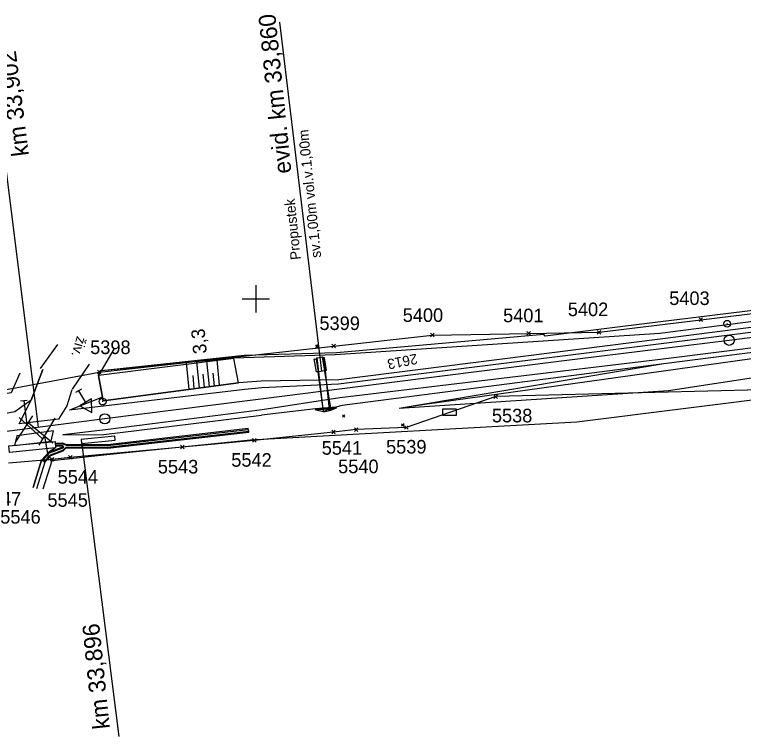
# Model space of a CAD drawing. Extents: x -805011 to -803920, y -1150790 to -1150234.
# Drawn here: x -804735.5 to -804628.3, y -1150564.4 to -1150458.2 of the extents above; entities that cross this region are included whole.
import ezdxf

# ---------------------------------------------------------------- set-up
doc = ezdxf.new("R2010")
doc.units = 0
for name, color, linetype in [('0381KM032-037P - Vrstva 1', 7, 'Continuous'), ('0381KM032-037P - Vrstva 13', 7, 'Continuous'), ('0381KM032-037P - Vrstva 17', 7, 'Continuous'), ('0381KM032-037P - Vrstva 19', 7, 'Continuous'), ('0381KM032-037P - Vrstva 25', 7, 'Continuous'), ('0381KM032-037P - Vrstva 4', 7, 'Continuous'), ('0381KM032-037P - Vrstva 43', 7, 'Continuous'), ('0381KM032-037P - Vrstva 48', 7, 'Continuous'), ('0381KM032-037P - Vrstva 49', 7, 'Continuous'), ('0381KM032-037P - Vrstva 51', 7, 'Continuous'), ('0381KM032-037P - Vrstva 57', 7, 'Continuous'), ('0381KM032-037P - Vrstva 7', 7, 'Continuous'), ('0381KM032-037P - Vrstva 9', 7, 'Continuous'), ('krizky_1000 - Vrstva 1', 7, 'Continuous'), ('szdc - hran DP', 7, 'Continuous'), ('szdc - szdc_cislo', 7, 'Continuous'), ('szdc - szdc_krizek', 7, 'Continuous')]:
    doc.layers.add(name, color=color, linetype=linetype)

msp = doc.modelspace()

# ---------------------------------------------------------------- linework, layer by layer
at = {"layer": '0381KM032-037P - Vrstva 1'}
msp.add_lwpolyline([(-804485.9, -1150487.74), (-804508.11, -1150490.55), (-804529.67, -1150493.3), (-804537.63, -1150494.31), (-804546.61, -1150495.46), (-804554.2, -1150496.42), (-804564.05, -1150497.67), (-804586.01, -1150500.48), (-804607.92, -1150503.26), (-804630.35, -1150506.11), (-804652.65, -1150508.9), (-804675.7, -1150511.78), (-804698.85, -1150514.71), (-804701.61, -1150515.06), (-804722.18, -1150517.67), (-804729.05, -1150518.54), (-804735.1, -1150519.31), (-804744.56, -1150520.5), (-804767.65, -1150523.46), (-804791, -1150526.42)], dxfattribs=at)
at = {"layer": '0381KM032-037P - Vrstva 13'}
for points in [[(-804703.22, -1150508.8), (-804723.12, -1150511.26), (-804722.46, -1150514.99), (-804702.53, -1150512.35), (-804703.22, -1150508.8)], [(-804732.2, -1150527.92), (-804730.97, -1150524.01), (-804730.13, -1150523.06), (-804728.33, -1150522.36), (-804727.9, -1150521.95), (-804721.78, -1150521.96), (-804701.01, -1150519.63), (-804701.03, -1150519.46), (-804701.1, -1150519.22), (-804701.1, -1150519.05)], [(-804731.12, -1150523.92), (-804730.21, -1150522.94), (-804728.39, -1150522.25), (-804727.91, -1150521.81), (-804721.79, -1150521.85), (-804701.03, -1150519.46)], [(-804729.45, -1150521.32), (-804728.46, -1150521.31), (-804727.91, -1150521.54), (-804721.8, -1150521.59), (-804701.1, -1150519.22)], [(-804729.38, -1150521.22), (-804728.48, -1150521.2), (-804727.92, -1150521.41), (-804721.8, -1150521.43), (-804701.1, -1150519.05)], [(-804732.74, -1150527.78), (-804731.51, -1150523.73), (-804730.41, -1150522.51), (-804728.49, -1150521.85), (-804728.25, -1150521.76), (-804728.53, -1150521.71), (-804729.44, -1150521.68)], [(-804731.32, -1150523.78), (-804730.35, -1150522.68), (-804728.48, -1150521.99), (-804728.25, -1150521.76), (-804728.5, -1150521.58), (-804729.42, -1150521.57)], [(-804729.38, -1150521.22), (-804729.45, -1150521.32), (-804729.42, -1150521.57), (-804729.44, -1150521.68)], [(-804731.51, -1150523.73), (-804731.32, -1150523.78), (-804731.12, -1150523.92), (-804730.97, -1150524.01)]]:
    msp.add_lwpolyline(points, dxfattribs=at)
at = {"layer": '0381KM032-037P - Vrstva 17'}
for p, q in [((-804731.66, -1150510.27), (-804729.1, -1150506.73)), ((-804726.96, -1150513.28), (-804724.46, -1150509.62))]:
    msp.add_line(p, q, dxfattribs=at)
for points in [[(-804552.89, -1150488.84), (-804553.29, -1150492.03), (-804593.3, -1150497.6), (-804640.86, -1150503.43), (-804657.42, -1150505.51), (-804657.62, -1150505.23), (-804688.14, -1150507.97), (-804701.71, -1150508.32), (-804722.68, -1150510.59), (-804720.85, -1150507.4)], [(-804731.29, -1150527.98), (-804729.95, -1150523.81), (-804721.9, -1150522.89), (-804700.75, -1150520.73), (-804652.77, -1150518.11), (-804588.21, -1150510.02), (-804572.8, -1150507.15), (-804561.55, -1150507.7), (-804553.92, -1150509.55)], [(-804734.71, -1150510.96), (-804735.96, -1150513.84), (-804741.77, -1150514.83), (-804760.36, -1150517.2), (-804793.92, -1150520.9)]]:
    msp.add_lwpolyline(points, dxfattribs=at)
at = {"layer": '0381KM032-037P - Vrstva 19'}
for p, q in [((-804690.3, -1150510.66), (-804696.47, -1150459.27)), ((-804690.02, -1150516.61), (-804690.96, -1150508.7)), ((-804688.92, -1150516.37), (-804690.16, -1150508.54)), ((-804690.09, -1150516.25), (-804690.83, -1150510.72)), ((-804689.77, -1150510.59), (-804689.19, -1150516.28)), ((-804690.02, -1150516.61), (-804688.92, -1150516.37))]:
    msp.add_line(p, q, dxfattribs=at)
for points in [[(-804689.58, -1150510.57), (-804689.77, -1150510.59), (-804690.83, -1150510.72), (-804691.04, -1150510.74), (-804691.4, -1150508.85), (-804691.12, -1150508.86), (-804690.83, -1150510.72)], [(-804691.12, -1150508.86), (-804690.96, -1150508.7), (-804690.59, -1150508.62), (-804690.16, -1150508.54), (-804690.08, -1150508.63)], [(-804689.58, -1150510.57), (-804689.88, -1150508.68), (-804690.08, -1150508.63), (-804689.77, -1150510.59)], [(-804688.16, -1150516.11), (-804688.92, -1150516.37), (-804689.19, -1150516.28), (-804690.09, -1150516.25), (-804690.02, -1150516.61), (-804691.14, -1150516.38)]]:
    msp.add_lwpolyline(points, dxfattribs=at)
msp.add_lwpolyline([(-804688.22, -1150515.92), (-804688.16, -1150516.11), (-804691.14, -1150516.38), (-804691.19, -1150516.18)], close=True, dxfattribs=at)
at = {"layer": '0381KM032-037P - Vrstva 25'}
msp.add_lwpolyline([(-804672.5, -1150517.17), (-804672.5, -1150516.17), (-804670.5, -1150516.17), (-804670.5, -1150517.17), (-804672.5, -1150517.17)], dxfattribs=at)
at = {"layer": '0381KM032-037P - Vrstva 4'}
for p, q in [((-804738.68, -1150465.82), (-804731.99, -1150518.9)), ((-804699.22, -1150512.12), (-804702.53, -1150512.35)), ((-804733.62, -1150514.94), (-804734.61, -1150515.06)), ((-804734.11, -1150515), (-804733.68, -1150518.47)), ((-804691.19, -1150516.18), (-804699.14, -1150517.12)), ((-804688.22, -1150515.92), (-804691.19, -1150516.18)), ((-804732.83, -1150517.21), (-804735.37, -1150521.05)), ((-804731.4, -1150520.55), (-804734.81, -1150517.46)), ((-804731.84, -1150521.52), (-804729.49, -1150517.55)), ((-804729.05, -1150518.54), (-804735.1, -1150519.31)), ((-804733.43, -1150518.25), (-804729.87, -1150521.17)), ((-804730.44, -1150523.66), (-804731.05, -1150520.21)), ((-804730.93, -1150523.75), (-804729.95, -1150523.57))]:
    msp.add_line(p, q, dxfattribs=at)
for points in [[(-804593.11, -1150499.86), (-804640.49, -1150505.94), (-804687.8, -1150511.91), (-804699.22, -1150512.12)], [(-804593.19, -1150500.62), (-804640.38, -1150506.6), (-804687.82, -1150512.54), (-804699.1, -1150513.12)], [(-804592.89, -1150502.96), (-804640.05, -1150508.88), (-804687.61, -1150514.59), (-804699.07, -1150516.32)], [(-804592.67, -1150503.55), (-804639.94, -1150509.55), (-804687.3, -1150515.71), (-804688.22, -1150515.92)], [(-804702.53, -1150512.35), (-804722.46, -1150514.99), (-804722.57, -1150514.49)], [(-804699.1, -1150513.12), (-804701.6, -1150513.32), (-804727.4, -1150516.37)], [(-804722.57, -1150514.49), (-804727.4, -1150516.37)], [(-804699.07, -1150516.32), (-804722.12, -1150519.29), (-804728.4, -1150520.02), (-804722.36, -1150519.97), (-804699.14, -1150517.12)]]:
    msp.add_lwpolyline(points, dxfattribs=at)
at = {"layer": '0381KM032-037P - Vrstva 43'}
msp.add_lwpolyline([(-804736.33, -1150521.65), (-804729.5, -1150520.98), (-804729.45, -1150521.92), (-804736.22, -1150522.62)], close=True, dxfattribs=at)
at = {"layer": '0381KM032-037P - Vrstva 48'}
for p, q in [((-804706.81, -1150512.92), (-804707.19, -1150509.11)), ((-804705.32, -1150512.72), (-804705.69, -1150508.97)), ((-804709.78, -1150513.31), (-804710.17, -1150509.4)), ((-804708.29, -1150513.12), (-804708.68, -1150509.26)), ((-804709.04, -1150513.21), (-804709.23, -1150511.27)), ((-804707.55, -1150513.02), (-804707.74, -1150511.1)), ((-804706.06, -1150512.82), (-804706.25, -1150510.93))]:
    msp.add_line(p, q, dxfattribs=at)
at = {"layer": '0381KM032-037P - Vrstva 49'}
for p, q in [((-804690.87, -1150506.79), (-804691.22, -1150507.14)), ((-804691.22, -1150506.79), (-804690.87, -1150507.14)), ((-804686.9, -1150517.05), (-804687.25, -1150517.41)), ((-804687.25, -1150517.05), (-804686.9, -1150517.41)), ((-804678.19, -1150518.41), (-804678.54, -1150518.76)), ((-804678.54, -1150518.41), (-804678.19, -1150518.76))]:
    msp.add_line(p, q, dxfattribs=at)
for points in [[(-804554.49, -1150494.02), (-804593.21, -1150499.01), (-804640.53, -1150505.12), (-804688.31, -1150508.22), (-804703.24, -1150508.74), (-804722.68, -1150510.59)], [(-804544.42, -1150497.94), (-804556.65, -1150501.33), (-804579.48, -1150502.32), (-804589.81, -1150503.62), (-804675.11, -1150515.57), (-804678.92, -1150516.15)], [(-804544.42, -1150497.94), (-804557.28, -1150504.11), (-804579.29, -1150503.91), (-804588.92, -1150505.83), (-804639.29, -1150513.56), (-804678.92, -1150516.15)], [(-804556.53, -1150499.44), (-804592.67, -1150503.55), (-804639.94, -1150509.55), (-804678.92, -1150516.15)], [(-804593.11, -1150499.86), (-804640.49, -1150505.94), (-804687.8, -1150511.91), (-804699.22, -1150512.12)], [(-804731.33, -1150510.42), (-804733.06, -1150514.89), (-804735.43, -1150516.61), (-804744.9, -1150518.34), (-804767.83, -1150521.26), (-804794.61, -1150523.51)], [(-804722.46, -1150514.99), (-804723.12, -1150511.26), (-804722.68, -1150510.59)], [(-804699.22, -1150512.12), (-804702.53, -1150512.35), (-804722.46, -1150514.99)], [(-804690.02, -1150516.61), (-804688.92, -1150516.37), (-804689.47, -1150516.35), (-804690.02, -1150516.61)]]:
    msp.add_lwpolyline(points, dxfattribs=at)
at = {"layer": '0381KM032-037P - Vrstva 51'}
msp.add_line((-804725.64, -1150513.28), (-804726.5, -1150513.8), dxfattribs=at)
for points in [[(-804727.06, -1150513.38), (-804727.78, -1150515.77), (-804729, -1150517.7), (-804734.83, -1150518.42), (-804733.06, -1150514.89), (-804731.33, -1150510.42)], [(-804726.07, -1150513.54), (-804725.04, -1150515.25), (-804725.9, -1150515.77), (-804724.14, -1150516.75), (-804724.18, -1150514.73), (-804725.04, -1150515.25)], [(-804729.45, -1150521.92), (-804730.41, -1150522.51), (-804731.51, -1150523.73), (-804732.74, -1150527.78)]]:
    msp.add_lwpolyline(points, dxfattribs=at)
msp.add_lwpolyline([(-804730.11, -1150520.97), (-804729.76, -1150519.41), (-804735.16, -1150520.17), (-804735.48, -1150521.58)], close=True, dxfattribs=at)
at = {"layer": '0381KM032-037P - Vrstva 7'}
for p, q in [((-804630.6, -1150503.66), (-804630.7, -1150503.68)), ((-804722.48, -1150515.11), (-804722.58, -1150515.12))]:
    msp.add_line(p, q, dxfattribs=at)
for centre, radius in [((-804630.65, -1150503.67), 0.5), ((-804630.34, -1150506.1), 0.75), ((-804722.53, -1150515.12), 0.5), ((-804722.2, -1150517.67), 0.75)]:
    msp.add_circle(centre, radius, dxfattribs=at)
at = {"layer": '0381KM032-037P - Vrstva 9'}
for p, q in [((-804720.72, -1150520.2), (-804725.69, -1150520.71)), ((-804725.69, -1150520.71), (-804725.63, -1150521.31)), ((-804725.66, -1150521.01), (-804720.15, -1150564.39)), ((-804725.63, -1150521.31), (-804720.66, -1150520.79)), ((-804720.66, -1150520.79), (-804720.72, -1150520.2)), ((-804725.63, -1150521.31), (-804725.57, -1150521.9))]:
    msp.add_line(p, q, dxfattribs=at)
at = {"layer": 'krizky_1000 - Vrstva 1'}
for points in [[(-804700, -1150498), (-804700, -1150502)], [(-804702, -1150500), (-804698, -1150500)]]:
    msp.add_lwpolyline(points, dxfattribs=at)
at = {"layer": 'szdc - hran DP'}
for p, q in [((-804634.52, -1150503.07), (-804621.33, -1150501.45)), ((-804649.49, -1150504.92), (-804634.52, -1150503.07)), ((-804659.84, -1150505.09), (-804649.49, -1150504.92)), ((-804688.55, -1150506.95), (-804674.03, -1150505.33)), ((-804674.03, -1150505.33), (-804659.84, -1150505.09)), ((-804723.03, -1150510.78), (-804688.55, -1150506.95)), ((-804747.72, -1150515.43), (-804723.03, -1150510.78)), ((-804621.63, -1150513.27), (-804664.68, -1150514.39)), ((-804664.68, -1150514.39), (-804677.85, -1150518.93)), ((-804688.56, -1150519.6), (-804700.23, -1150520.83)), ((-804685.22, -1150519.25), (-804688.56, -1150519.6)), ((-804677.85, -1150518.93), (-804685.22, -1150519.25)), ((-804700.23, -1150520.83), (-804710.79, -1150521.81)), ((-804710.79, -1150521.81), (-804727.28, -1150523.34)), ((-804729.97, -1150523.63), (-804736.36, -1150524.18)), ((-804727.28, -1150523.34), (-804729.97, -1150523.63))]:
    msp.add_line(p, q, dxfattribs=at)
at = {"layer": 'szdc - szdc_krizek'}
for p, q in [((-804634.26, -1150503.33), (-804634.79, -1150502.8)), ((-804634.79, -1150503.33), (-804634.26, -1150502.8)), ((-804659.58, -1150505.35), (-804660.11, -1150504.82)), ((-804660.11, -1150505.35), (-804659.58, -1150504.82)), ((-804649.22, -1150505.19), (-804649.76, -1150504.66)), ((-804649.76, -1150505.19), (-804649.22, -1150504.66)), ((-804673.77, -1150505.59), (-804674.3, -1150505.06)), ((-804674.3, -1150505.59), (-804673.77, -1150505.06)), ((-804688.29, -1150507.22), (-804688.82, -1150506.69)), ((-804688.82, -1150507.22), (-804688.29, -1150506.69)), ((-804722.77, -1150511.04), (-804723.3, -1150510.52)), ((-804723.3, -1150511.04), (-804722.77, -1150510.52)), ((-804664.42, -1150514.66), (-804664.95, -1150514.12)), ((-804664.95, -1150514.66), (-804664.42, -1150514.12)), ((-804677.58, -1150519.2), (-804678.12, -1150518.67)), ((-804678.12, -1150519.2), (-804677.58, -1150518.67)), ((-804688.3, -1150519.86), (-804688.83, -1150519.33)), ((-804688.83, -1150519.86), (-804688.3, -1150519.33)), ((-804684.96, -1150519.52), (-804685.49, -1150518.99)), ((-804685.49, -1150519.52), (-804684.96, -1150518.99)), ((-804699.96, -1150521.09), (-804700.5, -1150520.56)), ((-804700.5, -1150521.09), (-804699.96, -1150520.56)), ((-804710.53, -1150522.07), (-804711.06, -1150521.54)), ((-804711.06, -1150522.07), (-804710.53, -1150521.54)), ((-804727.02, -1150523.6), (-804727.55, -1150523.07)), ((-804727.55, -1150523.6), (-804727.02, -1150523.07)), ((-804729.71, -1150523.9), (-804730.24, -1150523.36)), ((-804730.24, -1150523.9), (-804729.71, -1150523.36))]:
    msp.add_line(p, q, dxfattribs=at)

# ---------------------------------------------------------------- texts
at = {"layer": '0381KM032-037P - Vrstva 19'}
for s, height, p in [('evid. km 33,860', 2.5, (-804694.74, -1150481.46)), ('sv.1,00m vol.v.1,00m', 1.5, (-804690.37, -1150493.89)), ('Propustek', 1.5, (-804693.36, -1150494.19))]:
    msp.add_text(s, height=height, rotation=95.8316, dxfattribs=at).set_placement(p)
at = {"layer": '0381KM032-037P - Vrstva 4'}
msp.add_text('km 33,902', height=2.5, rotation=97.1938, dxfattribs=at).set_placement((-804733.36, -1150478.88))
at = {"layer": '0381KM032-037P - Vrstva 48'}
msp.add_text('3,3', height=2, rotation=95.4373, dxfattribs=at).set_placement((-804707.19, -1150508.01))
at = {"layer": '0381KM032-037P - Vrstva 51'}
msp.add_text('živ.', height=1.5, rotation=253.3622, dxfattribs=at).set_placement((-804726.29, -1150505.42))
at = {"layer": '0381KM032-037P - Vrstva 57'}
msp.add_text('2613', height=1.5, rotation=191.1139, dxfattribs=at).set_placement((-804676.37, -1150508.07))
at = {"layer": '0381KM032-037P - Vrstva 9'}
msp.add_text('km 33,896', height=2.5, rotation=95.8904, dxfattribs=at).set_placement((-804721.45, -1150563.2))
at = {"layer": 'szdc - szdc_cislo'}
for s, p in [('5403', (-804639.17, -1150500.91)), ('5402', (-804654.09, -1150502.55)), ('5400', (-804678.38, -1150503.4)), ('5401', (-804663.61, -1150503.45)), ('5399', (-804690.63, -1150504.59)), ('5398', (-804724.36, -1150508.13)), ('5538', (-804665.26, -1150518.18)), ('5541', (-804690.3, -1150522.94)), ('5539', (-804680.83, -1150522.77)), ('5542', (-804703.6, -1150524.71)), ('5543', (-804714.41, -1150525.7)), ('5540', (-804687.88, -1150525.66)), ('5544', (-804729.15, -1150527.2)), ('5547', (-804740.45, -1150530.44)), ('5545', (-804730.65, -1150530.6)), ('5546', (-804737.59, -1150533.08))]:
    msp.add_text(s, height=2, dxfattribs=at).set_placement(p)

doc.saveas('drawing.dxf')
